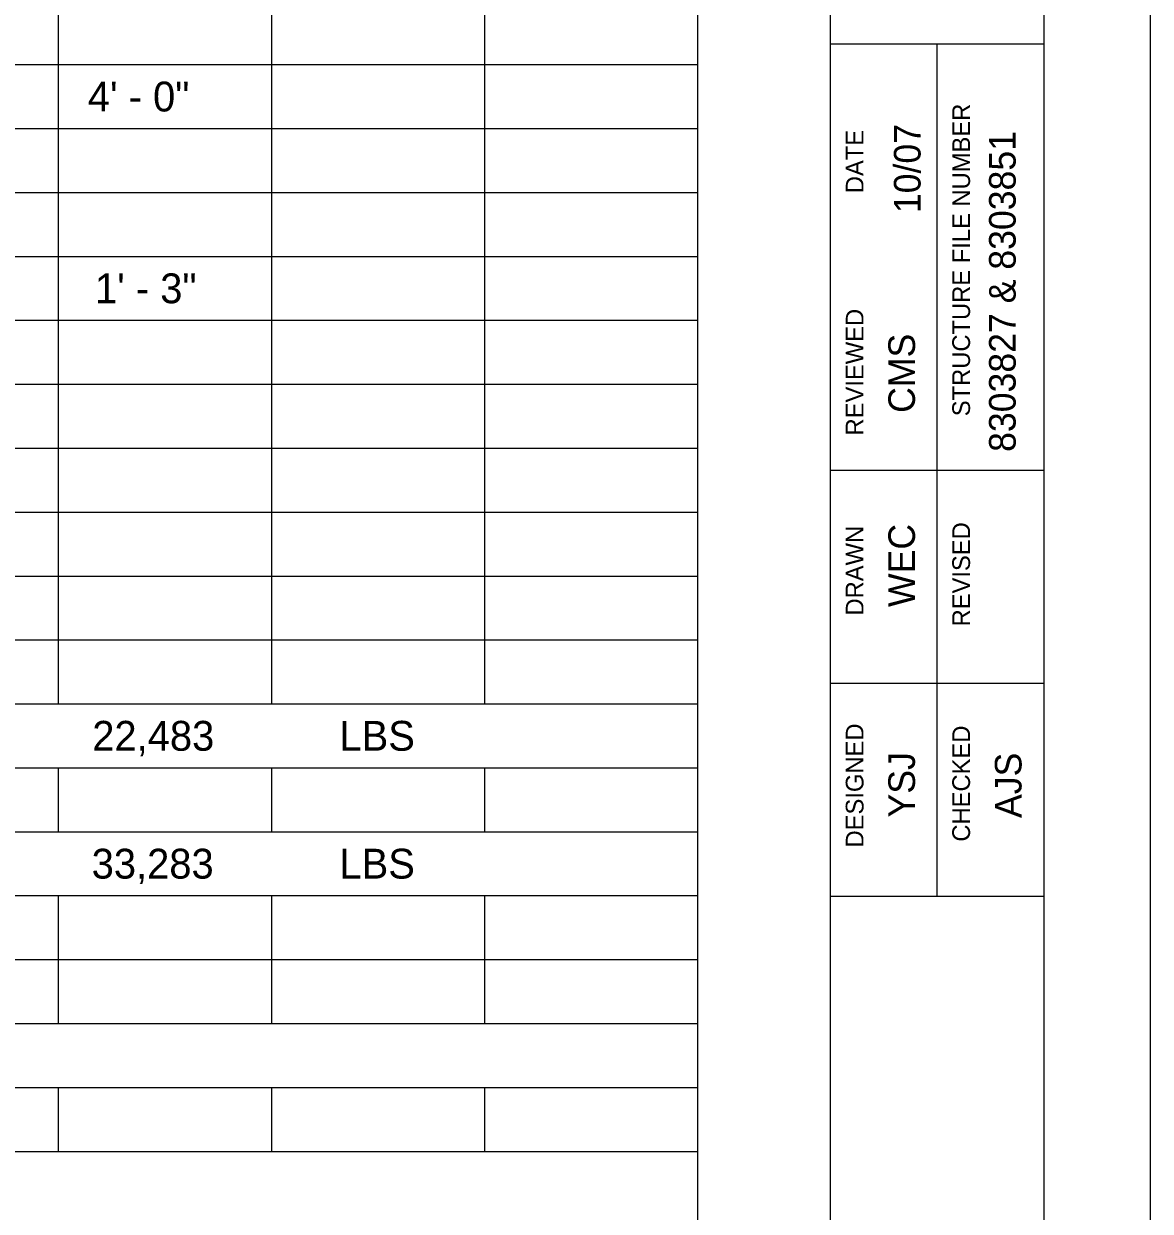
# Model space of a CAD drawing. Extents: x 1485751 to 1485785, y 230696.6 to 230718.6.
# Drawn here: x 1485779.75 to 1485785.03, y 230709.16 to 230714.74 of the extents above; entities that cross this region are included whole.
import ezdxf

# ---------------------------------------------------------------- set-up
doc = ezdxf.new("R2010")
doc.units = 0
for name, color, linetype in [('SH_Border', 7, 'Continuous'), ('SH_Cut_Line', 7, 'Continuous'), ('SH_Data', 7, 'Continuous'), ('TX_P_Misc', 7, 'Continuous')]:
    doc.layers.add(name, color=color, linetype=linetype)

msp = doc.modelspace()

# ---------------------------------------------------------------- linework, layer by layer
at = {"layer": 'SH_Border'}
for p, q in [((1485783.5329, 230697.1408), (1485783.5329, 230718.1408)), ((1485783.5329, 230697.1408), (1485783.5329, 230718.1408)), ((1485783.5329, 230697.1408), (1485783.5329, 230718.1408)), ((1485783.5329, 230714.6408), (1485784.5329, 230714.6408)), ((1485783.5329, 230714.6408), (1485784.5329, 230714.6408)), ((1485783.5329, 230714.6408), (1485784.5329, 230714.6408)), ((1485784.0329, 230710.6408), (1485784.0329, 230714.6408)), ((1485784.0329, 230710.6408), (1485784.0329, 230714.6408)), ((1485784.0329, 230710.6408), (1485784.0329, 230714.6408)), ((1485783.5329, 230712.6408), (1485784.5329, 230712.6408)), ((1485783.5329, 230712.6408), (1485784.5329, 230712.6408)), ((1485783.5329, 230712.6408), (1485784.5329, 230712.6408)), ((1485783.5329, 230711.6408), (1485784.5329, 230711.6408)), ((1485783.5329, 230711.6408), (1485784.5329, 230711.6408)), ((1485783.5329, 230711.6408), (1485784.5329, 230711.6408)), ((1485783.5329, 230710.6408), (1485784.5329, 230710.6408)), ((1485783.5329, 230710.6408), (1485784.5329, 230710.6408)), ((1485783.5329, 230710.6408), (1485784.5329, 230710.6408))]:
    msp.add_line(p, q, dxfattribs=at)
msp.add_lwpolyline([(1485753.0329, 230718.1408), (1485784.5329, 230718.1408), (1485784.5329, 230697.1408), (1485753.0329, 230697.1408)], close=True, dxfattribs=at)
at = {"layer": 'SH_Cut_Line'}
msp.add_lwpolyline([(1485751.0329, 230718.6408), (1485785.0329, 230718.6408), (1485785.0329, 230696.6408), (1485751.0329, 230696.6408)], close=True, dxfattribs=at)
at = {"layer": 'TX_P_Misc'}
for p, q in [((1485779.9079, 230717.394), (1485779.9079, 230711.544)), ((1485780.9079, 230717.394), (1485780.9079, 230711.544)), ((1485781.9079, 230717.394), (1485781.9079, 230711.544)), ((1485782.9079, 230717.394), (1485782.9079, 230699.244)), ((1485773.6579, 230714.544), (1485782.9079, 230714.544)), ((1485773.6579, 230714.244), (1485782.9079, 230714.244)), ((1485773.6579, 230713.944), (1485782.9079, 230713.944)), ((1485773.6579, 230713.644), (1485782.9079, 230713.644)), ((1485773.6579, 230713.344), (1485782.9079, 230713.344)), ((1485773.6579, 230713.044), (1485782.9079, 230713.044)), ((1485773.6579, 230712.744), (1485782.9079, 230712.744)), ((1485773.6579, 230712.444), (1485782.9079, 230712.444)), ((1485773.6579, 230712.144), (1485782.9079, 230712.144)), ((1485773.6579, 230711.844), (1485782.9079, 230711.844)), ((1485773.6579, 230711.544), (1485782.9079, 230711.544)), ((1485773.6579, 230711.244), (1485782.9079, 230711.244)), ((1485779.9079, 230711.244), (1485779.9079, 230710.944)), ((1485780.9079, 230711.244), (1485780.9079, 230710.944)), ((1485781.9079, 230711.244), (1485781.9079, 230710.944)), ((1485773.6579, 230710.944), (1485782.9079, 230710.944)), ((1485773.6579, 230710.644), (1485782.9079, 230710.644)), ((1485779.9079, 230710.644), (1485779.9079, 230710.044)), ((1485780.9079, 230710.644), (1485780.9079, 230710.044)), ((1485781.9079, 230710.644), (1485781.9079, 230710.044)), ((1485773.6579, 230710.344), (1485782.9079, 230710.344)), ((1485773.6579, 230710.044), (1485782.9079, 230710.044)), ((1485773.6579, 230709.744), (1485782.9079, 230709.744)), ((1485779.9079, 230709.744), (1485779.9079, 230709.444)), ((1485780.9079, 230709.744), (1485780.9079, 230709.444)), ((1485781.9079, 230709.744), (1485781.9079, 230709.444)), ((1485773.6579, 230709.444), (1485782.9079, 230709.444))]:
    msp.add_line(p, q, dxfattribs=at)

# ---------------------------------------------------------------- texts
at = {"layer": 'SH_Data'}
for s, height, p in [('STRUCTURE FILE NUMBER', 0.0833, (1485784.187, 230712.8938)), ('DATE', 0.0833, (1485783.687, 230713.9405)), ('10/07', 0.125, (1485783.9549, 230713.8469)), ('8303827 & 8303851', 0.125, (1485784.4012, 230712.7264)), ('REVIEWED', 0.0833, (1485783.687, 230712.8035)), ('CMS', 0.125, (1485783.9287, 230712.9095)), ('DRAWN', 0.0833, (1485783.687, 230711.9585)), ('WEC', 0.125, (1485783.9287, 230711.9985)), ('REVISED', 0.0833, (1485784.187, 230711.9073)), ('DESIGNED', 0.0833, (1485783.687, 230710.87)), ('CHECKED', 0.0833, (1485784.187, 230710.8975)), ('YSJ', 0.125, (1485783.9287, 230711.0108)), ('AJS', 0.125, (1485784.4287, 230711.0083))]:
    msp.add_text(s, height=height, rotation=90, dxfattribs=at).set_placement(p)
at = {"layer": 'TX_P_Misc'}
for s, p in [('4\' - 0"', (1485780.0463, 230714.324)), ('1\' - 3"', (1485780.08, 230713.424)), ('22,483', (1485780.0673, 230711.324)), ('LBS', (1485781.2276, 230711.324)), ('33,283', (1485780.0645, 230710.724)), ('LBS', (1485781.2276, 230710.724))]:
    msp.add_text(s, height=0.14, dxfattribs=at).set_placement(p)

doc.saveas('drawing.dxf')
